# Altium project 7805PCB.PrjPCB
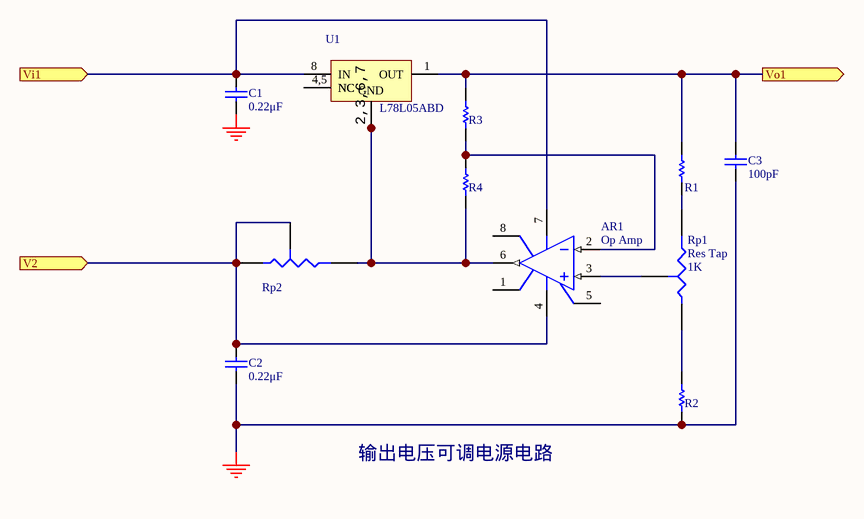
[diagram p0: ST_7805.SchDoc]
1 sheet, 11 parts. Net scope: flat (ports and power ports of the same name join across sheets).
Board file: 7805.PcbDoc

## Sheet ST_7805.SchDoc
size B

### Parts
AR1  Op Amp  [CAN-8/D9.4]
C1  0.22μF  [RAD-0.3]
C2  0.22μF  [RAD-0.3]
C3  value 100pF  [RAD-0.3]  (hidden comment: Cap)
R1  Res1  [AXIAL-0.3]  (value not drawn)
R2  Res1  [AXIAL-0.3]  (value not drawn)
R3  Res1  [AXIAL-0.3]  (value not drawn)
R4  Res1  [AXIAL-0.3]  (value not drawn)
Rp1  Res Tap  value 1K  [VR3]
Rp2  Res Tap  [VR3]  (value not drawn)
U1  L78L05ABD  [SO-G8]

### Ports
V2 (in), Vi1 (in), Vo1 (out)

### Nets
GND: C1.1 C2.1 C3.1 R2.1
NetAR1_2: AR1.2(IN-) R3.1 R4.2
NetAR1_3: AR1.3(IN+) Rp1.3(TAP)
NetAR1_4: AR1.4(V-) C2.2 Rp2.1(A) Rp2.3(TAP) ; port V2
NetAR1_6: AR1.6(OUT) R4.1 Rp2.2(B) U1.2(GND) U1.3(GND) U1.6(GND) U1.7(GND)
NetAR1_7: AR1.7(V+) C1.2 U1.8(IN) ; port Vi1
NetC3_2: C3.2 R1.2 R3.2 U1.1(OUT) ; port Vo1
NetR1_1: R1.1 Rp1.2(B)
NetR2_2: R2.2 Rp1.1(A)
NetU1_4: U1.4(NC) U1.5(NC)

Not connected (* = marked no-connect by the designer): AR1 1(OS_NUL) 5(OS_NUL) 8(TAB)

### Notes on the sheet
- 输出电压可调电源电路

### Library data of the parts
AR1 = Op Amp: FET Operational Amplifier; Manufacturer: Generic Components
C1-C3 = Cap: Capacitor; Manufacturer: Generic Components; Class I: Passive
R1-R4 = Res1: Resistor; Manufacturer: Generic Components; Class I: Passive; Value: 1K
Rp1 = Res Tap: Tapped Resistor; Manufacturer: Generic Components; Class I: Passive; Set Position: 0.5
Rp2 = Res Tap: Tapped Resistor; Manufacturer: Generic Components; Class I: Passive; Set Position: 0.5; Value: 1K
U1 = L78L05ABD: Positive Voltage Regulator; Manufacturer: ST-Microelectronics; Package Information: Latest Revision: Jul-1998; Class I: Power Management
